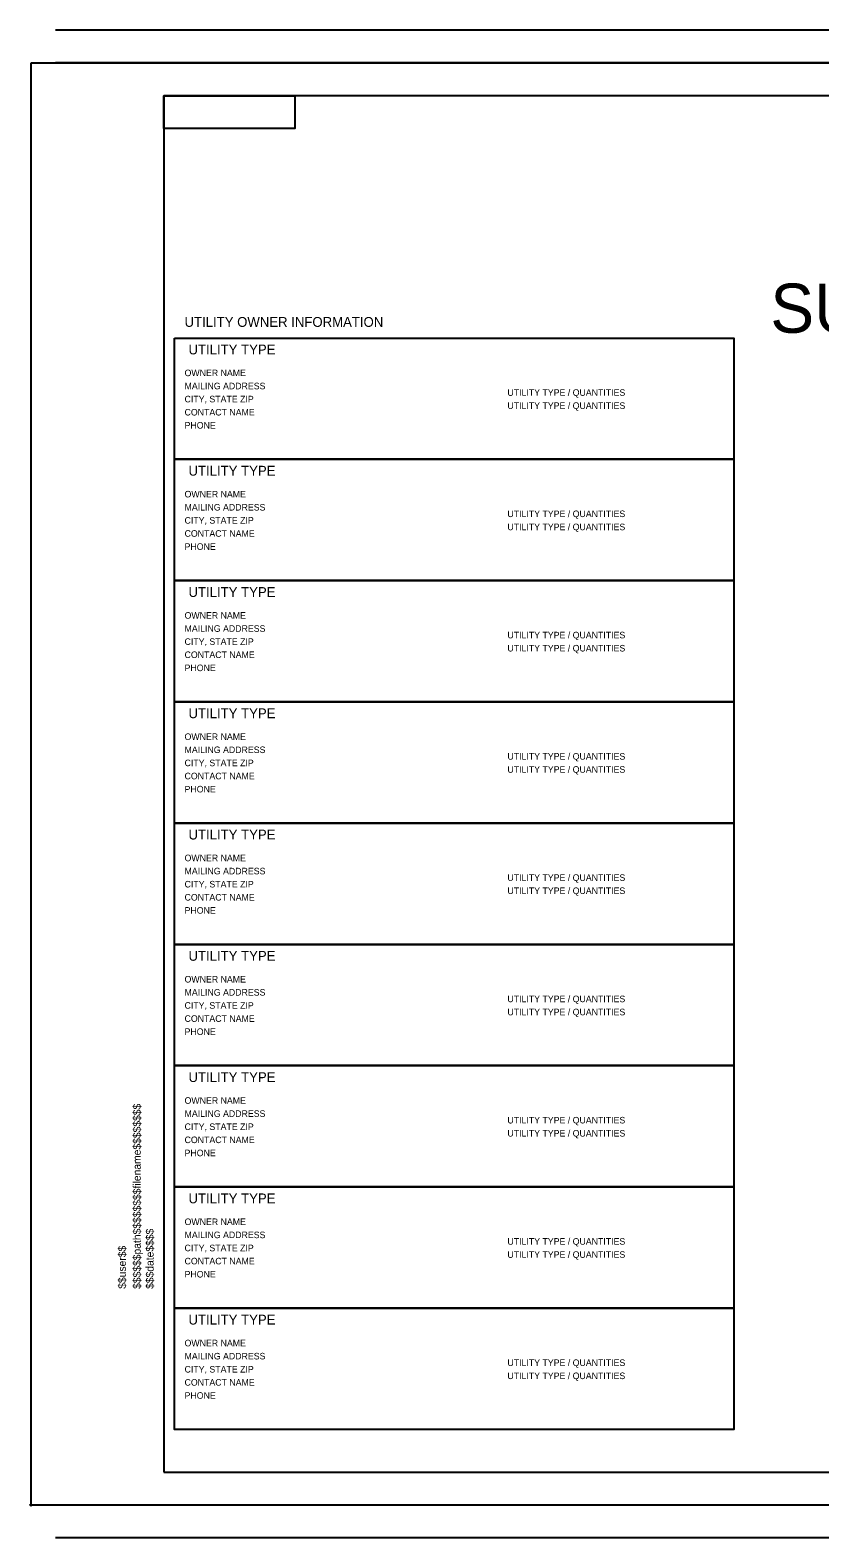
# Model space of a CAD drawing. Extents: x 189971 to 191767, y 195697 to 196847.
# Drawn here: x 189971 to 190573, y 195697 to 196847 of the extents above; entities that cross this region are included whole.
import ezdxf

# ---------------------------------------------------------------- set-up
doc = ezdxf.new("R2010")
doc.units = 0
for name, color, linetype in [('Default', 7, 'Continuous'), ('RD_SHT_Bndy', 7, 'Continuous'), ('RD_SHT_ID', 7, 'Continuous'), ('RD_SHT_Iplotshp', 7, 'Continuous'), ('RD_SHT_Snap', 7, 'Continuous'), ('RD_SHT_TX', 7, 'Continuous')]:
    doc.layers.add(name, color=color, linetype=linetype)

msp = doc.modelspace()

# ---------------------------------------------------------------- linework, layer by layer
at = {"layer": 'Default'}
msp.add_circle((189971.4, 195722.1), 0.607, dxfattribs=at)
at = {"layer": 'RD_SHT_Bndy'}
for p, q in [((191750, 196847.1), (189990, 196847.1)), ((191750, 196822.1), (189990, 196822.1)), ((191747.6, 196797.1), (190072.6, 196797.1)), ((190072.6, 196797.1), (190072.6, 195747.1)), ((190072.6, 195897.1), (190072.6, 195747.2)), ((190072.6, 195747.1), (191747.6, 195747.1)), ((191750, 195722.1), (189990, 195722.1)), ((191750, 195697.1), (189990, 195697.1))]:
    msp.add_line(p, q, dxfattribs=at)
for points in [[(190072.6, 196772.1), (190072.6, 196797.1), (190172.6, 196797.1), (190172.6, 196772.1)], [(190080.9, 196612.3), (190507.4, 196612.3), (190507.4, 196519.8), (190080.9, 196519.8)], [(190080.9, 196519.8), (190507.4, 196519.8), (190507.4, 196427.3), (190080.9, 196427.3)], [(190080.9, 196427.3), (190507.4, 196427.3), (190507.4, 196334.8), (190080.9, 196334.8)], [(190080.9, 196334.8), (190507.4, 196334.8), (190507.4, 196242.3), (190080.9, 196242.3)], [(190080.9, 196242.3), (190507.4, 196242.3), (190507.4, 196149.8), (190080.9, 196149.8)], [(190080.9, 196149.8), (190507.4, 196149.8), (190507.4, 196057.3), (190080.9, 196057.3)], [(190080.9, 196057.3), (190507.4, 196057.3), (190507.4, 195964.8), (190080.9, 195964.8)], [(190080.9, 195964.8), (190507.4, 195964.8), (190507.4, 195872.3), (190080.9, 195872.3)], [(190080.9, 195872.3), (190507.4, 195872.3), (190507.4, 195779.8), (190080.9, 195779.8)]]:
    msp.add_lwpolyline(points, close=True, dxfattribs=at)
at = {"layer": 'RD_SHT_Iplotshp'}
msp.add_lwpolyline([(189971.4, 196822.1), (191767.4, 196822.1), (191767.4, 195722.1), (189971.4, 195722.1)], close=True, dxfattribs=at)
at = {"layer": 'RD_SHT_Snap'}
msp.add_line((189971.4, 195722.1), (189971.4, 196822.1), dxfattribs=at)

# ---------------------------------------------------------------- texts
at = {"layer": 'Default'}
msp.add_text('SUBSURFACE UTILITY ENGINEERING', height=37.5, dxfattribs=at).set_placement((190535.2, 196616.3))
at = {"layer": 'RD_SHT_ID'}
for s, p in [('$$$$$$path$$$$$$$$filename$$$$$$$$', (190055.1, 195887)), ('$$$date$$$$', (190064.9, 195887)), ('$$user$$', (190043.8, 195887.1))]:
    msp.add_text(s, height=5.88, rotation=90, dxfattribs=at).set_placement(p)
at = {"layer": 'RD_SHT_TX'}
for s, height, p in [('UTILITY OWNER INFORMATION', 7.5, (190088.5, 196620.8)), ('UTILITY TYPE', 7.5, (190091.5, 196599.8)), ('OWNER NAME', 5, (190088.5, 196583.2)), ('MAILING ADDRESS', 5, (190088.5, 196573.2)), ('UTILITY TYPE / QUANTITIES', 5, (190334.7, 196568.2)), ('CITY, STATE ZIP', 5, (190088.5, 196563.2)), ('CONTACT NAME', 5, (190088.5, 196553.2)), ('UTILITY TYPE / QUANTITIES', 5, (190334.7, 196558.2)), ('PHONE', 5, (190088.5, 196543.2)), ('UTILITY TYPE', 7.5, (190091.5, 196507.3)), ('OWNER NAME', 5, (190088.5, 196490.7)), ('MAILING ADDRESS', 5, (190088.5, 196480.7)), ('UTILITY TYPE / QUANTITIES', 5, (190334.7, 196475.7)), ('CITY, STATE ZIP', 5, (190088.5, 196470.7)), ('UTILITY TYPE / QUANTITIES', 5, (190334.7, 196465.7)), ('CONTACT NAME', 5, (190088.5, 196460.7)), ('PHONE', 5, (190088.5, 196450.7)), ('UTILITY TYPE', 7.5, (190091.5, 196414.8)), ('OWNER NAME', 5, (190088.5, 196398.2)), ('MAILING ADDRESS', 5, (190088.5, 196388.2)), ('UTILITY TYPE / QUANTITIES', 5, (190334.7, 196383.2)), ('CITY, STATE ZIP', 5, (190088.5, 196378.2)), ('UTILITY TYPE / QUANTITIES', 5, (190334.7, 196373.2)), ('CONTACT NAME', 5, (190088.5, 196368.2)), ('PHONE', 5, (190088.5, 196358.2)), ('UTILITY TYPE', 7.5, (190091.5, 196322.3)), ('OWNER NAME', 5, (190088.5, 196305.7)), ('MAILING ADDRESS', 5, (190088.5, 196295.7)), ('UTILITY TYPE / QUANTITIES', 5, (190334.7, 196290.7)), ('CITY, STATE ZIP', 5, (190088.5, 196285.7)), ('UTILITY TYPE / QUANTITIES', 5, (190334.7, 196280.7)), ('CONTACT NAME', 5, (190088.5, 196275.7)), ('PHONE', 5, (190088.5, 196265.7)), ('UTILITY TYPE', 7.5, (190091.5, 196229.8)), ('OWNER NAME', 5, (190088.5, 196213.2)), ('MAILING ADDRESS', 5, (190088.5, 196203.2)), ('UTILITY TYPE / QUANTITIES', 5, (190334.7, 196198.2)), ('CITY, STATE ZIP', 5, (190088.5, 196193.2)), ('UTILITY TYPE / QUANTITIES', 5, (190334.7, 196188.2)), ('CONTACT NAME', 5, (190088.5, 196183.2)), ('PHONE', 5, (190088.5, 196173.2)), ('UTILITY TYPE', 7.5, (190091.5, 196137.3)), ('OWNER NAME', 5, (190088.5, 196120.7)), ('MAILING ADDRESS', 5, (190088.5, 196110.7)), ('UTILITY TYPE / QUANTITIES', 5, (190334.7, 196105.7)), ('CITY, STATE ZIP', 5, (190088.5, 196100.7)), ('UTILITY TYPE / QUANTITIES', 5, (190334.7, 196095.7)), ('CONTACT NAME', 5, (190088.5, 196090.7)), ('PHONE', 5, (190088.5, 196080.7)), ('UTILITY TYPE', 7.5, (190091.5, 196044.8)), ('OWNER NAME', 5, (190088.5, 196028.2)), ('MAILING ADDRESS', 5, (190088.5, 196018.2)), ('UTILITY TYPE / QUANTITIES', 5, (190334.7, 196013.2)), ('CITY, STATE ZIP', 5, (190088.5, 196008.2)), ('UTILITY TYPE / QUANTITIES', 5, (190334.7, 196003.2)), ('CONTACT NAME', 5, (190088.5, 195998.2)), ('PHONE', 5, (190088.5, 195988.2)), ('UTILITY TYPE', 7.5, (190091.5, 195952.3)), ('OWNER NAME', 5, (190088.5, 195935.7)), ('MAILING ADDRESS', 5, (190088.5, 195925.7)), ('UTILITY TYPE / QUANTITIES', 5, (190334.7, 195920.7)), ('CITY, STATE ZIP', 5, (190088.5, 195915.7)), ('UTILITY TYPE / QUANTITIES', 5, (190334.7, 195910.7)), ('CONTACT NAME', 5, (190088.5, 195905.7)), ('PHONE', 5, (190088.5, 195895.7)), ('UTILITY TYPE', 7.5, (190091.5, 195859.8)), ('OWNER NAME', 5, (190088.5, 195843.2)), ('MAILING ADDRESS', 5, (190088.5, 195833.2)), ('CITY, STATE ZIP', 5, (190088.5, 195823.2)), ('UTILITY TYPE / QUANTITIES', 5, (190334.7, 195828.2)), ('UTILITY TYPE / QUANTITIES', 5, (190334.7, 195818.2)), ('CONTACT NAME', 5, (190088.5, 195813.2)), ('PHONE', 5, (190088.5, 195803.2))]:
    msp.add_text(s, height=height, dxfattribs=at).set_placement(p)

doc.saveas('drawing.dxf')
